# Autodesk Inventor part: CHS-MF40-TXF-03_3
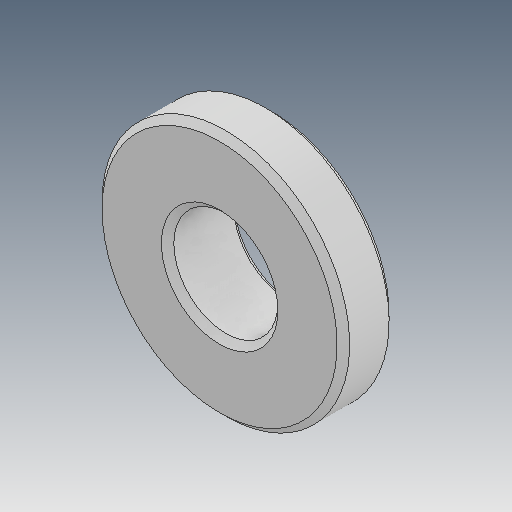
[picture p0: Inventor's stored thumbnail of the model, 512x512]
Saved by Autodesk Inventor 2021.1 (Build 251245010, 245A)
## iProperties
Created: 2019-04
Part Number: CHS-MF40-TXF-03_3
Material: Ogólny
Document SubType Name: Modeling
Designer: user
Density: 1 g/cm^3
Appearance: Domyślna
Author: user
Revision Number: ÈÎºÎ
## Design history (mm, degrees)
feature "ÊäÈë1"
node "Bryła1"
